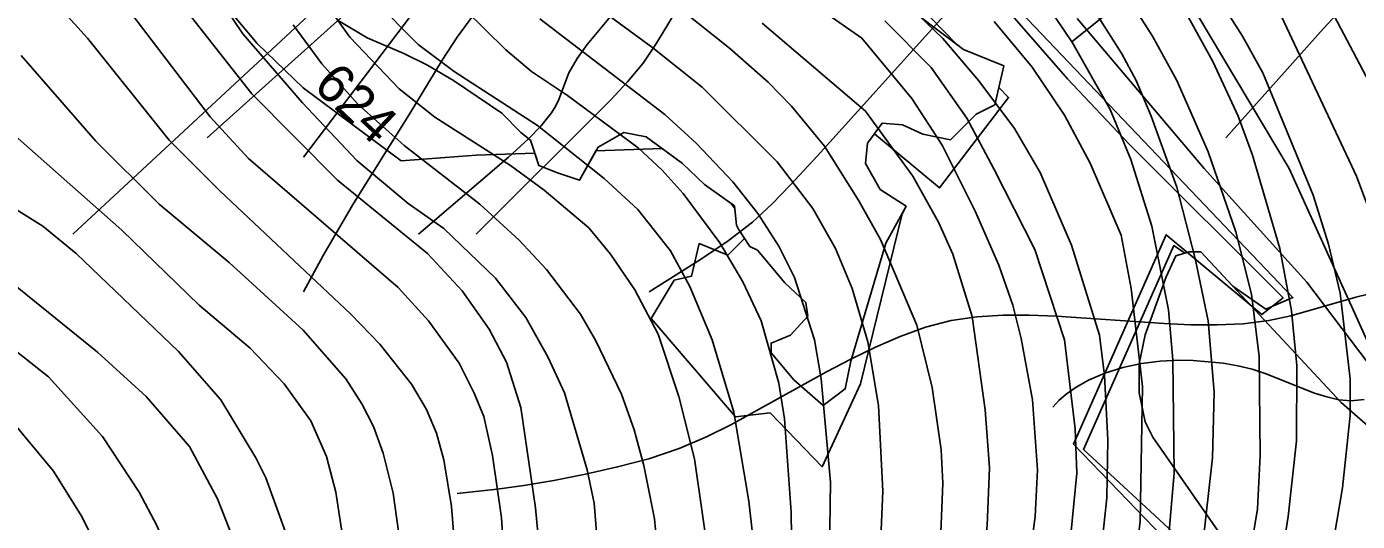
# Model space of a CAD drawing. Extents: x -709584 to -702006, y -1161789 to -1157496.
# Drawn here: x -708051.5 to -707705.2, y -1159704.2 to -1159575.6 of the extents above; entities that cross this region are included whole.
import ezdxf

# ---------------------------------------------------------------- set-up
doc = ezdxf.new("R2010")
doc.units = 0
for name, color, linetype in [('102_obvod PÚ', 7, 'Continuous'), ('120_vrstevnice hlavní', 7, 'Continuous'), ('121_vrstevnice hlavní_popis', 7, 'Continuous'), ('122_vrstevnice základní', 7, 'Continuous'), ('408_BPEJ_linie', 7, 'Continuous'), ('411_akumulovaný odtok', 7, 'Continuous'), ('419_LPIS PB', 7, 'Continuous')]:
    doc.layers.add(name, color=color, linetype=linetype)

msp = doc.modelspace()

# ---------------------------------------------------------------- linework, layer by layer
at = {"layer": '102_obvod PÚ'}
msp.add_lwpolyline([(-707670.93, -1159922.8), (-707731.59, -1159911.86), (-707763.37, -1159913.49), (-707796.59, -1159905.07), (-707818.87, -1159893.49), (-707825.94, -1159873.58), (-707828.15, -1159838.47), (-707837.5, -1159806.43), (-707835.31, -1159806.35), (-707824.97, -1159837.6), (-707819.37, -1159821.29), (-707807.56, -1159823.44), (-707800.43, -1159801.21), (-707768.65, -1159765.65), (-707741.59, -1159722.96), (-707779.05, -1159684.11), (-707754.95, -1159629.68), (-707730.06, -1159650.46), (-707724.56, -1159646.08), (-707764.64, -1159606.18), (-707780.62, -1159589.13), (-707816.59, -1159548.02)], dxfattribs=at)
at = {"layer": '120_vrstevnice hlavní'}
for points in [[(-707927.94, -1159703.28), (-707930.25, -1159687.08), (-707932.52, -1159676.93), (-707935.03, -1159670.88), (-707938.93, -1159663.07), (-707946.89, -1159652.07), (-707954.84, -1159643.4), (-707993.75, -1159609.84), (-708003.73, -1159598.99), (-708027.74, -1159567.46), (-708039.32, -1159553.14), (-708044.23, -1159545.62), (-708052.48, -1159530.57)], [(-707961.06, -1159568.61), (-707949.64, -1159580.19), (-707940.23, -1159587.27), (-707918.54, -1159601.3), (-707901.18, -1159615.05), (-707892.5, -1159623.15), (-707883.97, -1159633.85), (-707878.9, -1159643.11), (-707873.12, -1159656.99), (-707867.48, -1159675.8), (-707863.57, -1159698.94), (-707862.56, -1159708.2), (-707862.41, -1159726.71), (-707863.14, -1159745.23), (-707864.87, -1159759.11), (-707868.34, -1159782.26), (-707871.38, -1159796.14), (-707874.85, -1159819.28), (-707884.83, -1159860.94), (-707887.87, -1159879.46), (-707891.34, -1159907.23), (-707892.36, -1159925.74), (-707892.21, -1159939.63)], [(-707786.04, -1159569.92), (-707779.39, -1159579.75), (-707769.55, -1159597.11), (-707764.2, -1159610.13), (-707758.7, -1159627.49), (-707754.37, -1159649.18), (-707753.21, -1159662.2), (-707752.92, -1159691.71), (-707754.37, -1159708.78)], [(-707726.3, -1159570.21), (-707705.48, -1159614.47), (-707699.4, -1159630.67)], [(-707860.1, -1159574.69), (-707833.2, -1159597.54), (-707820.9, -1159614.47), (-707814.1, -1159626.62), (-707810.49, -1159634.72), (-707805.42, -1159650.92), (-707802.1, -1159675.22), (-707800.94, -1159690.26), (-707801.52, -1159705.3), (-707804.27, -1159731.63), (-707806.44, -1159742.91), (-707817.43, -1159782.26), (-707838.26, -1159851.11), (-707841.01, -1159866.73), (-707841.15, -1159878.01), (-707839.42, -1159894.21), (-707836.52, -1159910.41), (-707834.06, -1159918.51), (-707827.27, -1159930.66)], [(-708060.87, -1159637.76), (-708033.09, -1159660.18), (-708020.37, -1159671.75), (-708009.08, -1159684.77), (-708001.85, -1159698.36), (-707997.08, -1159710.51), (-707993.9, -1159722.66), (-707988.4, -1159763.16), (-707985.94, -1159797.88), (-707985.94, -1159832.01), (-707984.49, -1159849.37), (-707981.6, -1159871.07), (-707979.87, -1159879.75), (-707972.06, -1159910.12), (-707968.44, -1159931.82)], [(-707930.11, -1159936.16), (-707931.7, -1159919.96), (-707932.57, -1159879.46), (-707931.99, -1159867.31), (-707929.09, -1159842.43), (-707927.94, -1159816.39), (-707927.36, -1159775.02), (-707926.35, -1159727.58), (-707927.94, -1159703.28)]]:
    msp.add_lwpolyline(points, dxfattribs=at)
at = {"layer": '122_vrstevnice základní'}
for points in [[(-707919.12, -1159700.68), (-707922.88, -1159674.64), (-707926.64, -1159662.78), (-707931.12, -1159654.25), (-707938.21, -1159644.26), (-707947.18, -1159634.57), (-707970.61, -1159615.48), (-707992.88, -1159593.06), (-708009.52, -1159571.94), (-708025.72, -1159549.09), (-708036.13, -1159530.86), (-708041.2, -1159518.71), (-708045.97, -1159504.54), (-708051.46, -1159484.29), (-708058.7, -1159467.51)], [(-708071.86, -1159538.67), (-708035.7, -1159578.6), (-708014.44, -1159605.07), (-708001.27, -1159618.23), (-707967.14, -1159650.34), (-707959.62, -1159658.15), (-707951.37, -1159668.56), (-707947.42, -1159675.11), (-707944.86, -1159681.29), (-707942.98, -1159688.24), (-707940.96, -1159700.39), (-707939.8, -1159714.27), (-707940.09, -1159735.97), (-707939.08, -1159758.82), (-707937.92, -1159843.58), (-707938.21, -1159872.22), (-707940.52, -1159908.68), (-707940.23, -1159916.78), (-707936.76, -1159943.1)], [(-707755.38, -1159546.2), (-707735.13, -1159578.02), (-707729.78, -1159587.56), (-707716.76, -1159619.39), (-707712.71, -1159632.11), (-707709.67, -1159644.84), (-707707.07, -1159667.12), (-707707.07, -1159676.67), (-707709.09, -1159695.47), (-707711.26, -1159708.2), (-707715.02, -1159720.93), (-707729.2, -1159762.29), (-707735.27, -1159776.76), (-707743.95, -1159802.79), (-707746.27, -1159814.37), (-707746.55, -1159823.33), (-707744.96, -1159832.88), (-707742.5, -1159839.25), (-707736.28, -1159848.79), (-707729.78, -1159855.01), (-707723.27, -1159858.77), (-707718.06, -1159860.65), (-707710.25, -1159861.67), (-707685.95, -1159862.68)], [(-707717.77, -1159560.37), (-707698.1, -1159597.69)], [(-707889.03, -1159564.85), (-707868.63, -1159581.2), (-707858.51, -1159590.02), (-707852.43, -1159596.24), (-707843.9, -1159606.66), (-707834.93, -1159620.83), (-707829.29, -1159630.96), (-707819.89, -1159653.23), (-707815.84, -1159669.43), (-707813.52, -1159685.63), (-707813.09, -1159694.31), (-707813.96, -1159715.72), (-707815.69, -1159731.92), (-707821.62, -1159756.22), (-707839.85, -1159816.1), (-707848.09, -1159852.55), (-707850.99, -1159870.49), (-707851.85, -1159892.76), (-707851.13, -1159906.94), (-707849.11, -1159917.06), (-707844.77, -1159929.21)], [(-707768.83, -1159561.82), (-707758.56, -1159578.02), (-707752.2, -1159589.59), (-707744.09, -1159608.1), (-707736.86, -1159628.93), (-707732.81, -1159645.13), (-707730.79, -1159661.33), (-707730.5, -1159687.08), (-707731.22, -1159700.97), (-707733.1, -1159712.54)], [(-707917.23, -1159929.21), (-707916.51, -1159904.62), (-707910.58, -1159861.81), (-707902.77, -1159790.36), (-707901.18, -1159753.91), (-707901.47, -1159728.45), (-707903.78, -1159699.52), (-707905.66, -1159690.84), (-707911.57, -1159670.82), (-707915.79, -1159661.62), (-707921.57, -1159651.21), (-707929.53, -1159640.94), (-707942.98, -1159628.06), (-707952.24, -1159621.55), (-707965.55, -1159610.42), (-707979.72, -1159595.37), (-707995.2, -1159577.44), (-708002.58, -1159566.45)], [(-707901.18, -1159939.92), (-707901.18, -1159917.64), (-707900.6, -1159906.07), (-707893.66, -1159860.94), (-707882.38, -1159806.27), (-707880.35, -1159788.04), (-707877.02, -1159767.5), (-707873.12, -1159734.23), (-707873.7, -1159715.72), (-707877.75, -1159687.95), (-707881.8, -1159671.75), (-707887.15, -1159655.55), (-707893.22, -1159643.98), (-707899.59, -1159634.72), (-707905.23, -1159627.92), (-707916.8, -1159618.08), (-707925.62, -1159611.72), (-707945.3, -1159599.14), (-707954.55, -1159591.76), (-707967.43, -1159578.31), (-707975.67, -1159566.74)], [(-707942.84, -1159565.72), (-707926.78, -1159581.63), (-707920.13, -1159587.27), (-707910.73, -1159593.49), (-707892.36, -1159607.09), (-707886.14, -1159612.88), (-707880.64, -1159618.95), (-707871.09, -1159631.82), (-707865.16, -1159641.95), (-707860.39, -1159652.07), (-707855.76, -1159668.28), (-707854.31, -1159677.53), (-707852.58, -1159701.83), (-707852.29, -1159720.93), (-707859.09, -1159782.54), (-707861.98, -1159796.43), (-707868.92, -1159838.09), (-707873.41, -1159857.18), (-707877.75, -1159879.17), (-707881.51, -1159909.54), (-707881.65, -1159925.74), (-707880.21, -1159939.92)], [(-707854.75, -1159933.26), (-707858.94, -1159914.46), (-707859.81, -1159902.89), (-707860.1, -1159888.42), (-707859.38, -1159878.3), (-707855.91, -1159853.71), (-707839.99, -1159777.34), (-707836.09, -1159751.01), (-707831.6, -1159728.74), (-707829.29, -1159710.51), (-707828.71, -1159696.34), (-707829.87, -1159674.06), (-707832.62, -1159657.57), (-707836.67, -1159643.69), (-707841.01, -1159633.27), (-707846.94, -1159622.86), (-707856.2, -1159610.71), (-707875.72, -1159591.32), (-707888.59, -1159581.05), (-707906.1, -1159568.18)], [(-707790.96, -1159717.17), (-707789.08, -1159702.99), (-707788.5, -1159690.84), (-707789.8, -1159672.61), (-707792.7, -1159656.7), (-707794.87, -1159648.03), (-707798.48, -1159637.61), (-707804.56, -1159623.73), (-707813.23, -1159606.37), (-707821.19, -1159594.22), (-707834.21, -1159578.6), (-707849.83, -1159567.61)], [(-707771.72, -1159710.22), (-707770.42, -1159698.07), (-707770.13, -1159683.03), (-707771, -1159666.25), (-707772.3, -1159655.84), (-707779.64, -1159632.36), (-707787.74, -1159613.53), (-707794.44, -1159602.07), (-707803.69, -1159589.67), (-707813.07, -1159578.68), (-707825.61, -1159566.64)], [(-707773.89, -1159571.07), (-707766.52, -1159582.65), (-707762.75, -1159589.59), (-707758.85, -1159598.85), (-707752.2, -1159617.36), (-707747.42, -1159635.88), (-707744.09, -1159652.07), (-707742.5, -1159670.59), (-707742.94, -1159687.66), (-707745.54, -1159710.8)], [(-707701.28, -1159872.8), (-707716.9, -1159870.2), (-707729.49, -1159865.28), (-707734.84, -1159861.95), (-707743.37, -1159854.72), (-707748, -1159849.08), (-707750.46, -1159845.03), (-707753.5, -1159836.93), (-707754.8, -1159830.86), (-707755.38, -1159824.78), (-707754.8, -1159814.37), (-707753.06, -1159802.22), (-707750.75, -1159794.12), (-707732.52, -1159747.54), (-707727.03, -1159727.29), (-707723.27, -1159702.99), (-707721.1, -1159683.32), (-707720.95, -1159663.65), (-707722.4, -1159649.47), (-707725.44, -1159633.27), (-707732.52, -1159608.97), (-707736.28, -1159598.85), (-707742.79, -1159584.67), (-707750.6, -1159570.5)], [(-707982.18, -1159575.12), (-707974.66, -1159585.25), (-707965.26, -1159595.81), (-707953.25, -1159606.51), (-707933.58, -1159621.7), (-707923.31, -1159631.1), (-707916.22, -1159638.77), (-707907.4, -1159650.34), (-707903.35, -1159657.28), (-707896.7, -1159671.17), (-707893.37, -1159680.43), (-707890.91, -1159689.68), (-707888.16, -1159703.57), (-707886.86, -1159717.46), (-707886.86, -1159729.03), (-707892.5, -1159796.14), (-707896.55, -1159828.83), (-707905.81, -1159889.58), (-707907.83, -1159919.96), (-707907.83, -1159942.23)], [(-707917.96, -1159573.53), (-707885.41, -1159598.41), (-707877.17, -1159605.93), (-707867.77, -1159615.91), (-707861.26, -1159624.16), (-707855.76, -1159632.69), (-707851.71, -1159640.79), (-707846.5, -1159656.99), (-707844.77, -1159667.12), (-707842.31, -1159694.02), (-707842.6, -1159711.96), (-707845.35, -1159750.14), (-707848.82, -1159776.47), (-707859.81, -1159837.22), (-707866.18, -1159860.07), (-707869.79, -1159882.35), (-707870.66, -1159892.47), (-707870.51, -1159902.6), (-707867.91, -1159922.85), (-707863.28, -1159941.07)], [(-707828.2, -1159574.03), (-707816.17, -1159586.22), (-707806.82, -1159599.38), (-707799.82, -1159612.51), (-707789.19, -1159633.57), (-707781.41, -1159656.99), (-707778.67, -1159680.14), (-707778.23, -1159691.71), (-707779.82, -1159707.62), (-707785.75, -1159735.1), (-707795.59, -1159768.37), (-707810.05, -1159810.32), (-707814.83, -1159826.23), (-707818.01, -1159843.87), (-707818.15, -1159856.02), (-707817.29, -1159866.44), (-707812.95, -1159889), (-707807.31, -1159908.1), (-707803.69, -1159916.78), (-707799.21, -1159925.45), (-707792.12, -1159935.72)], [(-707799.71, -1159574.26), (-707789.84, -1159586.1), (-707781.47, -1159598.59), (-707774.78, -1159611.06), (-707766.66, -1159629.8), (-707764.06, -1159643.69), (-707761.16, -1159669.14), (-707761.74, -1159704.15), (-707763.91, -1159722.66)], [(-708052.91, -1159583.08), (-708033.53, -1159605.36), (-708017.04, -1159621.7), (-707998.81, -1159636.89), (-707979.58, -1159654.53), (-707968.44, -1159667.12), (-707964.24, -1159673.63), (-707961.21, -1159679.56), (-707958.75, -1159686.5), (-707956.14, -1159696.92), (-707953.69, -1159714.27), (-707953.54, -1159737.71), (-707951.8, -1159784.57), (-707948.62, -1159829.7), (-707948.77, -1159849.08), (-707948.04, -1159881.77), (-707946.31, -1159911.28), (-707941.68, -1159952.65)], [(-707993.32, -1159659.16), (-708006.62, -1159648.03), (-708026.73, -1159628.5), (-708072.58, -1159588)], [(-708067.52, -1159614.9), (-708047.27, -1159627.49), (-708038.59, -1159634.57), (-708011.98, -1159660.03), (-708000.98, -1159672.61), (-707991.87, -1159687.66), (-707989.27, -1159692.86), (-707984.21, -1159706.75), (-707981.02, -1159718.9), (-707979.43, -1159727.58), (-707977.41, -1159751.88), (-707977.41, -1159764.32), (-707976.39, -1159784.28), (-707974.8, -1159798.46), (-707969.31, -1159871.36), (-707964.68, -1159903.76), (-707957.88, -1159940.21), (-707955.57, -1159948.31), (-707952.09, -1159964.22), (-707946.31, -1159981.57), (-707935.46, -1160004.14), (-707925.05, -1160023.23)], [(-707999.1, -1159828.25), (-708004.31, -1159754.48), (-708006.19, -1159742.91), (-708012.84, -1159716.88), (-708017.62, -1159705.3), (-708022.25, -1159696.63), (-708031.79, -1159682.16), (-708045.82, -1159666.68), (-708057.11, -1159657.72)], [(-707950.5, -1159941.36), (-707953.54, -1159920.53), (-707955.85, -1159899.71), (-707956.14, -1159888.14), (-707959.18, -1159857.47), (-707960.77, -1159829.12), (-707963.23, -1159808.87), (-707964.53, -1159792.67), (-707967.14, -1159722.08), (-707971.04, -1159696.63), (-707973.5, -1159687.37), (-707977.55, -1159678.11), (-707984.49, -1159668.42), (-707993.32, -1159659.16)], [(-708056.82, -1159676.38), (-708044.52, -1159691.13), (-708037.29, -1159702.7), (-708034.4, -1159708.49), (-708025.14, -1159731.63), (-708022.1, -1159741.18), (-708017.18, -1159760.27), (-708014.87, -1159773), (-708012.99, -1159788.91), (-708010.82, -1159836.64), (-708009.23, -1159855.45), (-708003.44, -1159881.48), (-707998.38, -1159898.84), (-707985.36, -1159936.45)], [(-707922.44, -1159940.5), (-707922.88, -1159917.35), (-707921.72, -1159884.08), (-707917.67, -1159849.08), (-707917.23, -1159835.77), (-707915.07, -1159813.79), (-707916.66, -1159726.71), (-707919.12, -1159700.68)]]:
    msp.add_lwpolyline(points, dxfattribs=at)
at = {"layer": '408_BPEJ_linie'}
for points in [[(-707674, -1159765), (-707676.5, -1159752), (-707680, -1159734), (-707700.5, -1159662), (-707723, -1159612.5), (-707774, -1159527), (-707827, -1159459.5), (-707852, -1159419), (-707870, -1159378.5), (-707876.5, -1159346.5), (-707877.8, -1159340.96)], [(-708030.5, -1159533.5), (-707991.5, -1159580), (-707979.5, -1159591.5), (-707954, -1159610.5), (-707934.5, -1159609), (-707919.26, -1159608.45), (-707918.2, -1159611.7), (-707913.4, -1159613.6), (-707907.6, -1159615.5), (-707903.35, -1159607.88), (-707886.15, -1159607.26), (-707880.8, -1159611.2), (-707875.1, -1159616.6), (-707868.18, -1159621.55), (-707867.22, -1159622.84), (-707866.78, -1159627.22), (-707866.28, -1159628.22), (-707864.66, -1159630.66), (-707869, -1159635), (-707876.5, -1159632), (-707878.5, -1159640.5), (-707883, -1159641.5), (-707889, -1159651.5), (-707867, -1159677), (-707858, -1159676), (-707844.5, -1159690), (-707834.5, -1159668.5), (-707823.69, -1159624.27), (-707822.6, -1159622.3), (-707829.4, -1159617.9), (-707833.2, -1159611.2), (-707832.7, -1159605.9), (-707830.89, -1159603.42), (-707814, -1159617.5), (-707796, -1159594), (-707798.53, -1159591.41), (-707797.2, -1159585.8), (-707807.71, -1159581.51), (-707809.52, -1159580.15), (-707816.5, -1159573)], [(-707814, -1159549.5), (-707722, -1159646), (-707729, -1159649), (-707737.66, -1159643.04), (-707745.97, -1159634.14), (-707748.97, -1159634.14), (-707750.13, -1159634.47), (-707753, -1159632.5), (-707776.5, -1159685.5), (-707737, -1159722)]]:
    msp.add_lwpolyline(points, dxfattribs=at)
at = {"layer": '411_akumulovaný odtok'}
msp.add_line((-707979.49, -1159609.5), (-707931.99, -1159547), dxfattribs=at)
for points in [[(-707739.49, -1159604.5), (-707714, -1159576.04), (-707704.68, -1159565.9), (-707695.64, -1159556.72), (-707689.25, -1159551.09), (-707685.88, -1159548.52), (-707682.35, -1159546.19), (-707678.69, -1159544.03), (-707671.12, -1159540.06), (-707651.73, -1159530.81), (-707644.11, -1159526.93), (-707636.82, -1159522.64), (-707633.39, -1159520.22), (-707630.37, -1159517.76), (-707627.48, -1159515.13), (-707621.95, -1159509.54), (-707611.03, -1159498.05), (-707604.66, -1159492.1), (-707597.48, -1159485.99), (-707588.68, -1159478.89), (-707566.99, -1159462)], [(-708039.49, -1159629.5), (-707914.24, -1159513.29), (-707907.28, -1159506.33), (-707899.87, -1159498.23), (-707893.34, -1159490.36), (-707886.99, -1159482)], [(-707889.49, -1159644.5), (-707876.11, -1159636.09), (-707868.99, -1159631.25), (-707862.65, -1159626.42), (-707857.53, -1159621.68), (-707852.73, -1159616.74), (-707845.72, -1159609.14), (-707766.99, -1159522)], [(-707949.49, -1159629.5), (-707926.09, -1159609.49), (-707920.91, -1159604.77), (-707917.72, -1159601.5), (-707914.94, -1159598.03), (-707913.82, -1159596.18), (-707913.04, -1159594.52), (-707910.37, -1159587.63), (-707908.22, -1159583.83), (-707905.61, -1159580.19), (-707898.24, -1159571.4), (-707871.99, -1159542)], [(-707934.49, -1159629.5), (-707899.51, -1159594.64), (-707895.11, -1159589.96), (-707891.11, -1159585.05), (-707887.63, -1159579.9), (-707884.35, -1159574.59), (-707881.22, -1159569.2), (-707878.33, -1159563.7), (-707876.63, -1159559.48), (-707875.05, -1159554.37), (-707871.99, -1159542)], [(-708004.49, -1159604.5), (-707966.51, -1159570.47), (-707958.23, -1159563.37), (-707955.32, -1159561.21), (-707950.76, -1159558.22), (-707931.99, -1159547)], [(-707779.49, -1159579.5), (-707762.02, -1159565.4)], [(-707979.49, -1159644.5), (-707974.34, -1159635.12), (-707966.42, -1159621.6), (-707952.03, -1159598.58), (-707943.37, -1159584.3), (-707939.45, -1159578.28), (-707935.37, -1159572.76)], [(-707939.49, -1159697), (-707929.02, -1159695.87), (-707922.16, -1159694.91), (-707914.35, -1159693.62), (-707906.04, -1159691.98), (-707897.72, -1159690.04), (-707889.59, -1159687.93), (-707881.68, -1159685.28), (-707874.56, -1159682.26), (-707868.3, -1159679.09), (-707843.32, -1159665.35), (-707837, -1159662.03), (-707830.62, -1159658.91), (-707824.17, -1159656.12), (-707817.62, -1159653.76), (-707810.93, -1159652.01), (-707804.24, -1159651.02), (-707797.42, -1159650.6), (-707790.51, -1159650.58), (-707783.55, -1159650.84), (-707755.53, -1159652.78), (-707748.58, -1159653.09), (-707741.69, -1159653.14), (-707734.9, -1159652.84), (-707728.23, -1159652.02), (-707722.52, -1159650.8), (-707705.64, -1159645.91), (-707686.37, -1159641.28)], [(-707784.49, -1159674.5), (-707782.94, -1159672.77), (-707780.99, -1159671.15), (-707778.38, -1159669.31), (-707775.17, -1159667.48), (-707770.94, -1159665.67), (-707766.26, -1159664.23), (-707761.38, -1159663.19), (-707756.53, -1159662.53), (-707751.98, -1159662.26), (-707747.93, -1159662.36), (-707740.14, -1159663.11), (-707736.32, -1159663.77), (-707732.57, -1159664.68), (-707729.23, -1159665.76), (-707716.36, -1159670.85), (-707713.19, -1159671.86), (-707710.04, -1159672.58), (-707706.88, -1159672.86), (-707703.44, -1159672.57)]]:
    msp.add_lwpolyline(points, dxfattribs=at)
at = {"layer": '419_LPIS PB'}
for points in [[(-707819.72, -1159572.47), (-707807.71, -1159581.51), (-707797.2, -1159585.8), (-707799.6, -1159595.9), (-707804.4, -1159598.3), (-707811.1, -1159605), (-707818.3, -1159603.5), (-707823.6, -1159601.1), (-707828.9, -1159600.7), (-707832.7, -1159605.9), (-707833.2, -1159611.2), (-707829.4, -1159617.9), (-707822.6, -1159622.3), (-707827.9, -1159631.9), (-707837, -1159662.6), (-707838.5, -1159669.8), (-707844.2, -1159674.1), (-707851.9, -1159667.4), (-707857.77, -1159660.36), (-707857.77, -1159657.85), (-707852.76, -1159655.84), (-707848.26, -1159650.82), (-707848.76, -1159647.3), (-707854.2, -1159642.2), (-707861.28, -1159633.74), (-707863.28, -1159632.74), (-707866.28, -1159628.22), (-707866.78, -1159627.22), (-707867.28, -1159622.19), (-707875.1, -1159616.6), (-707880.8, -1159611.2), (-707890.3, -1159604.2), (-707896.1, -1159603.1), (-707902.8, -1159606.9), (-707907.6, -1159615.5), (-707913.4, -1159613.6), (-707918.2, -1159611.7), (-707920.35, -1159605.12), (-707922.86, -1159603.11), (-707927.86, -1159598.09), (-707940.38, -1159589.55), (-707947.38, -1159585.53), (-707953.39, -1159582.52), (-707962.9, -1159578.5), (-707970.41, -1159573.98)], [(-707697.8, -1159669.14), (-707718.33, -1159642.02), (-707745.1, -1159612.5), (-707778.1, -1159573.5)], [(-707741.48, -1159706.73), (-707758.48, -1159682.34), (-707760.48, -1159678.33), (-707761.99, -1159670.8), (-707761.99, -1159663.26), (-707760.48, -1159655.73), (-707754.98, -1159640.67), (-707752.48, -1159635.15), (-707748.97, -1159634.14), (-707745.97, -1159634.14), (-707709.43, -1159673.31), (-707678.4, -1159700.42)]]:
    msp.add_lwpolyline(points, dxfattribs=at)

# ---------------------------------------------------------------- texts
at = {"layer": '121_vrstevnice hlavní_popis'}
msp.add_text('624', height=10, rotation=316.5966, dxfattribs=at).set_placement((-707977.23, -1159591.39))

doc.saveas('drawing.dxf')
